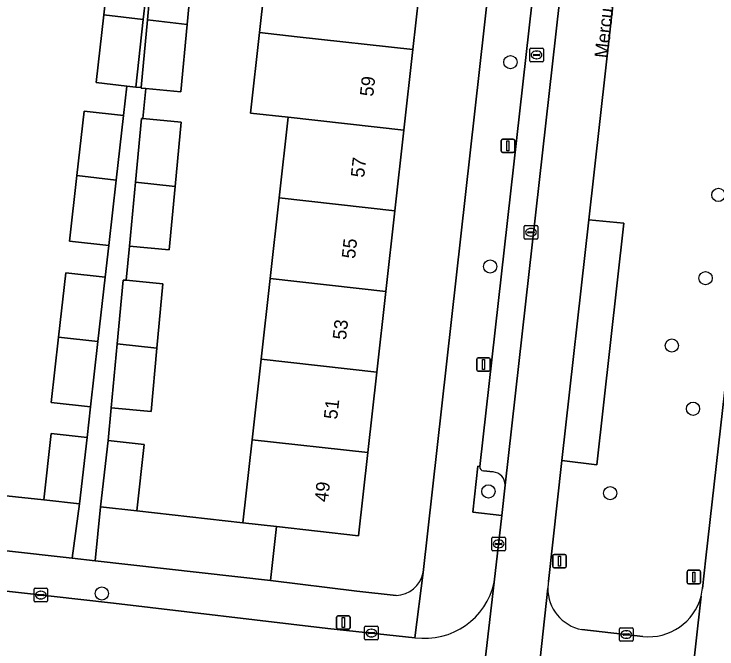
# Model space of a CAD drawing. Extents: x 161928 to 163071, y 386474 to 387428.
# Drawn here: x 162242.6 to 162294.6, y 386837.4 to 386884.4 of the extents above; entities that cross this region are included whole.
import ezdxf

# ---------------------------------------------------------------- set-up
doc = ezdxf.new("R2010")
doc.units = 0
for name, color, linetype in [('IMGEO_Berm_groen', 7, 'Continuous'), ('IMGEO_Boom', 7, 'Continuous'), ('IMGEO_Erf', 7, 'Continuous'), ('IMGEO_Groenvoorziening', 7, 'Continuous'), ('IMGEO_Kolk', 7, 'Continuous'), ('IMGEO_Lichtmast', 7, 'Continuous'), ('IMGEO_Openbare_ruimte_label', 7, 'Continuous'), ('IMGEO_Pand', 7, 'Continuous'), ('IMGEO_Pand_nummerreeks', 7, 'Continuous'), ('IMGEO_Parkeervlak_open', 7, 'Continuous'), ('IMGEO_Rijbaan_lokaal_open', 7, 'Continuous'), ('IMGEO_Rioolput', 7, 'Continuous'), ('IMGEO_Voetpad_open', 7, 'Continuous')]:
    doc.layers.add(name, color=color, linetype=linetype)

msp = doc.modelspace()

# ---------------------------------------------------------------- linework, layer by layer
at = {"layer": 'IMGEO_Berm_groen'}
for points in [[(162295.85, 386964.979), (162295.462, 386961.436), (162295.08, 386957.884), (162297.642, 386957.598), (162295.617, 386939.703), (162293.056, 386940.001), (162285.144, 386869.204), (162287.724, 386868.941), (162285.731, 386851.066), (162283.151, 386851.378), (162282.158, 386842.431)], [(162293.554, 386841.928), (162293.809, 386844.193), (162299.377, 386893.49), (162296.758, 386893.764), (162298.724, 386911.513)], [(162277.087, 386850.951), (162276.936, 386850.98), (162276.572, 386847.562), (162278.711, 386847.315), (162278.952, 386849.57)], [(162278.064, 386850.541), (162277.348, 386850.619)], [(162284.621, 386838.88), (162289.132, 386838.377)]]:
    msp.add_lwpolyline(points, dxfattribs=at)
for centre, radius, start, end in [((162277.388, 386850.919), 0.303, 173.9352, 262.4098), ((162278.011, 386849.601), 0.942, 358.1276, 86.7595), ((162285.107, 386841.925), 2.993, 170.2592, 179.4386), ((162285.207, 386841.916), 3.092, 179.2985, 259.0771), ((162289.496, 386842.369), 4.082, 345.7335, 353.7996), ((162289.577, 386842.351), 3.999, 263.6065, 345.6982)]:
    msp.add_arc(centre, radius, start, end, dxfattribs=at)
at = {"layer": 'IMGEO_Boom'}
for centre in [(162279.345, 386880.858), (162294.728, 386871.036), (162277.85, 386865.738), (162293.78, 386864.88), (162291.285, 386859.891), (162292.851, 386855.219), (162277.718, 386849.103), (162286.725, 386848.967), (162249.13, 386841.548)]:
    msp.add_circle(centre, 0.489, dxfattribs=at)
at = {"layer": 'IMGEO_Erf'}
for points in [[(162272.9, 386843.099), (162279.836, 386905.223), (162274.804, 386905.82), (162274.118, 386899.673), (162273.453, 386893.71), (162272.788, 386887.747), (162272.123, 386881.784), (162271.458, 386875.822), (162270.793, 386869.859), (162270.128, 386863.896), (162269.462, 386857.933), (162268.797, 386851.97), (162268.112, 386845.826), (162262.05, 386846.502), (162261.606, 386842.521), (162267.991, 386841.725), (162270.892, 386841.406)], [(162255.855, 386888.118), (162255.441, 386883.655), (162254.978, 386878.665), (162252.382, 386878.905), (162252.176, 386876.679), (162255.001, 386876.417), (162254.559, 386871.653), (162254.124, 386866.963), (162251.177, 386867.237), (162250.944, 386864.718), (162253.65, 386864.467), (162253.208, 386859.703), (162252.773, 386855.013), (162249.826, 386855.287), (162249.589, 386852.863), (162252.264, 386852.565), (162251.718, 386847.674), (162259.56, 386846.78), (162260.246, 386852.925), (162260.911, 386858.888), (162261.576, 386864.851), (162262.241, 386870.814), (162262.907, 386876.777), (162260.12, 386877.088), (162260.785, 386883.05), (162261.45, 386889.013)], [(162236.439, 386849.378), (162244.833, 386848.474), (162245.382, 386853.393), (162248.038, 386853.096), (162248.306, 386855.351), (162245.392, 386855.677), (162245.933, 386860.521), (162246.464, 386865.276), (162249.378, 386864.951), (162249.657, 386867.301), (162246.743, 386867.627), (162247.284, 386872.471), (162247.815, 386877.226), (162250.729, 386876.901), (162250.974, 386879.094), (162248.715, 386879.346), (162249.274, 386884.348), (162249.773, 386888.811)], [(162252.699, 386888.484), (162252.2, 386884.015), (162251.642, 386879.019), (162252.034, 386878.983), (162252.498, 386883.981), (162252.908, 386888.391)]]:
    msp.add_lwpolyline(points, dxfattribs=at)
msp.add_arc((162270.815, 386843.534), 2.13, 272.0613, 348.209, dxfattribs=at)
at = {"layer": 'IMGEO_Groenvoorziening'}
for points in [[(162246.945, 386844.164), (162247.49, 386848.178), (162244.833, 386848.474), (162236.439, 386849.378), (162231.888, 386849.896), (162231.457, 386845.899)], [(162261.606, 386842.521), (162262.05, 386846.502), (162259.56, 386846.78), (162251.718, 386847.674), (162249.043, 386847.972), (162248.649, 386843.973)]]:
    msp.add_lwpolyline(points, close=True, dxfattribs=at)
at = {"layer": 'IMGEO_Kolk'}
for p, q in [((162280.367, 386867.845), (162280.367, 386868.697)), ((162280.442, 386868.771), (162281.294, 386868.771)), ((162281.368, 386868.697), (162281.368, 386867.845)), ((162280.626, 386868.265), (162280.626, 386868.277)), ((162281.064, 386868.228), (162280.666, 386868.228)), ((162280.669, 386868.314), (162281.067, 386868.314)), ((162280.855, 386868.551), (162280.88, 386868.551)), ((162281.11, 386868.277), (162281.11, 386868.265)), ((162281.294, 386867.771), (162280.442, 386867.771)), ((162280.878, 386867.991), (162280.853, 386867.991)), ((162278.047, 386845.717), (162278.899, 386845.717)), ((162277.972, 386844.791), (162277.972, 386845.643)), ((162278.231, 386845.211), (162278.231, 386845.223)), ((162278.669, 386845.174), (162278.271, 386845.174)), ((162278.274, 386845.26), (162278.672, 386845.26)), ((162278.46, 386845.497), (162278.485, 386845.497)), ((162278.715, 386845.223), (162278.715, 386845.211)), ((162278.973, 386845.643), (162278.973, 386844.791)), ((162278.899, 386844.717), (162278.047, 386844.717)), ((162278.483, 386844.937), (162278.458, 386844.937)), ((162244.118, 386841.01), (162244.118, 386841.862)), ((162244.193, 386841.936), (162245.045, 386841.936)), ((162244.606, 386841.716), (162244.631, 386841.716)), ((162245.119, 386841.862), (162245.119, 386841.01)), ((162244.377, 386841.43), (162244.377, 386841.442)), ((162244.815, 386841.393), (162244.417, 386841.393)), ((162244.42, 386841.479), (162244.818, 386841.479)), ((162244.629, 386841.156), (162244.604, 386841.156)), ((162244.861, 386841.442), (162244.861, 386841.43)), ((162245.045, 386840.936), (162244.193, 386840.936)), ((162268.566, 386838.199), (162268.566, 386839.051)), ((162268.641, 386839.125), (162269.493, 386839.125)), ((162269.567, 386839.051), (162269.567, 386838.199)), ((162287.411, 386838.09), (162287.411, 386838.942)), ((162287.486, 386839.016), (162288.338, 386839.016)), ((162288.412, 386838.942), (162288.412, 386838.09)), ((162268.825, 386838.619), (162268.825, 386838.631)), ((162269.263, 386838.582), (162268.865, 386838.582)), ((162268.868, 386838.668), (162269.266, 386838.668)), ((162269.054, 386838.905), (162269.079, 386838.905)), ((162269.309, 386838.631), (162269.309, 386838.619)), ((162287.67, 386838.51), (162287.67, 386838.522)), ((162288.108, 386838.473), (162287.71, 386838.473)), ((162287.713, 386838.559), (162288.111, 386838.559)), ((162287.899, 386838.796), (162287.924, 386838.796)), ((162288.154, 386838.522), (162288.154, 386838.51)), ((162269.493, 386838.125), (162268.641, 386838.125)), ((162269.077, 386838.345), (162269.052, 386838.345)), ((162288.338, 386838.016), (162287.486, 386838.016)), ((162287.922, 386838.236), (162287.897, 386838.236))]:
    msp.add_line(p, q, dxfattribs=at)
for points in [[(162280.367, 386867.845), (162280.367, 386868.697)], [(162280.442, 386868.771), (162281.294, 386868.771)], [(162281.368, 386868.697), (162281.368, 386867.845)], [(162281.294, 386867.771), (162280.442, 386867.771)], [(162278.047, 386845.717), (162278.899, 386845.717)], [(162277.972, 386844.791), (162277.972, 386845.643)], [(162278.973, 386845.643), (162278.973, 386844.791)], [(162278.899, 386844.717), (162278.047, 386844.717)], [(162244.118, 386841.01), (162244.118, 386841.862)], [(162244.193, 386841.936), (162245.045, 386841.936)], [(162245.119, 386841.862), (162245.119, 386841.01)], [(162245.045, 386840.936), (162244.193, 386840.936)], [(162268.566, 386838.199), (162268.566, 386839.051)], [(162268.641, 386839.125), (162269.493, 386839.125)], [(162269.567, 386839.051), (162269.567, 386838.199)], [(162287.411, 386838.09), (162287.411, 386838.942)], [(162287.486, 386839.016), (162288.338, 386839.016)], [(162288.412, 386838.942), (162288.412, 386838.09)], [(162269.493, 386838.125), (162268.641, 386838.125)], [(162288.338, 386838.016), (162287.486, 386838.016)]]:
    msp.add_lwpolyline(points, dxfattribs=at)
for centre, radius, start, end in [((162280.444, 386868.695), 0.0765, 91.552, 178.448), ((162280.444, 386868.695), 0.0765, 91.552, 178.448), ((162281.292, 386868.695), 0.0765, 1.552, 88.448), ((162281.292, 386868.695), 0.0765, 1.552, 88.448), ((162280.666, 386868.274), 0.0403, 85.8775, 175.7526), ((162280.663, 386868.264), 0.0366, 178.938, 274.7102), ((162281.067, 386868.271), 0.043, 264.8664, 352.4533), ((162281.071, 386868.276), 0.0386, 1.7309, 96.639), ((162280.444, 386867.847), 0.0765, 181.552, 268.448), ((162280.444, 386867.847), 0.0765, 181.552, 268.448), ((162281.292, 386867.847), 0.0765, 271.552, 358.448), ((162281.292, 386867.847), 0.0765, 271.552, 358.448), ((162278.049, 386845.641), 0.0765, 91.552, 178.448), ((162278.049, 386845.641), 0.0765, 91.552, 178.448), ((162278.897, 386845.641), 0.0765, 1.552, 88.448), ((162278.897, 386845.641), 0.0765, 1.552, 88.448), ((162278.271, 386845.22), 0.0403, 85.8775, 175.7526), ((162278.268, 386845.21), 0.0366, 178.938, 274.7102), ((162278.672, 386845.217), 0.043, 264.8664, 352.4533), ((162278.676, 386845.222), 0.0386, 1.7309, 96.639), ((162278.049, 386844.793), 0.0765, 181.552, 268.448), ((162278.049, 386844.793), 0.0765, 181.552, 268.448), ((162278.897, 386844.793), 0.0765, 271.552, 358.448), ((162278.897, 386844.793), 0.0765, 271.552, 358.448), ((162244.195, 386841.86), 0.0765, 91.552, 178.448), ((162244.195, 386841.86), 0.0765, 91.552, 178.448), ((162245.043, 386841.86), 0.0765, 1.552, 88.448), ((162245.043, 386841.86), 0.0765, 1.552, 88.448), ((162244.195, 386841.012), 0.0765, 181.552, 268.448), ((162244.195, 386841.012), 0.0765, 181.552, 268.448), ((162244.417, 386841.439), 0.0403, 85.8775, 175.7526), ((162244.414, 386841.429), 0.0366, 178.938, 274.7102), ((162244.818, 386841.436), 0.043, 264.8664, 352.4533), ((162244.822, 386841.441), 0.0386, 1.7309, 96.639), ((162245.043, 386841.012), 0.0765, 271.552, 358.448), ((162245.043, 386841.012), 0.0765, 271.552, 358.448), ((162268.643, 386839.049), 0.0765, 91.552, 178.448), ((162268.643, 386839.049), 0.0765, 91.552, 178.448), ((162269.491, 386839.049), 0.0765, 1.552, 88.448), ((162269.491, 386839.049), 0.0765, 1.552, 88.448), ((162287.488, 386838.94), 0.0765, 91.552, 178.448), ((162287.488, 386838.94), 0.0765, 91.552, 178.448), ((162288.336, 386838.94), 0.0765, 1.552, 88.448), ((162288.336, 386838.94), 0.0765, 1.552, 88.448), ((162268.865, 386838.628), 0.0403, 85.8775, 175.7526), ((162268.862, 386838.618), 0.0366, 178.938, 274.7102), ((162269.266, 386838.625), 0.043, 264.8664, 352.4533), ((162269.27, 386838.63), 0.0386, 1.7309, 96.639), ((162287.71, 386838.519), 0.0403, 85.8775, 175.7526), ((162287.707, 386838.509), 0.0366, 178.938, 274.7102), ((162288.111, 386838.516), 0.043, 264.8664, 352.4533), ((162288.115, 386838.521), 0.0386, 1.7309, 96.639), ((162268.643, 386838.201), 0.0765, 181.552, 268.448), ((162268.643, 386838.201), 0.0765, 181.552, 268.448), ((162269.491, 386838.201), 0.0765, 271.552, 358.448), ((162269.491, 386838.201), 0.0765, 271.552, 358.448), ((162287.488, 386838.092), 0.0765, 181.552, 268.448), ((162287.488, 386838.092), 0.0765, 181.552, 268.448), ((162288.336, 386838.092), 0.0765, 271.552, 358.448), ((162288.336, 386838.092), 0.0765, 271.552, 358.448)]:
    msp.add_arc(centre, radius, start, end, dxfattribs=at)
for centre, major_axis, ratio, start_param, end_param in [((162280.854, 386868.271), (-0.387, 0.002), 0.722429, 4.712389, 7.853982), ((162280.879, 386868.271), (-0.39, 0.002), 0.717154, 1.570796, 4.712389), ((162278.459, 386845.217), (-0.387, 0.002), 0.722429, 4.712389, 7.853982), ((162278.484, 386845.217), (-0.39, 0.002), 0.717154, 1.570796, 4.712389), ((162244.605, 386841.436), (-0.387, 0.002), 0.722429, 4.712389, 7.853982), ((162244.63, 386841.436), (-0.39, 0.002), 0.717154, 1.570796, 4.712389), ((162269.053, 386838.625), (-0.387, 0.002), 0.722429, 4.712389, 7.853982), ((162269.078, 386838.625), (-0.39, 0.002), 0.717154, 1.570796, 4.712389), ((162287.898, 386838.516), (-0.387, 0.002), 0.722429, 4.712389, 7.853982), ((162287.923, 386838.516), (-0.39, 0.002), 0.717154, 1.570796, 4.712389)]:
    msp.add_ellipse(centre, major_axis=major_axis, ratio=ratio, start_param=start_param, end_param=end_param, dxfattribs=at)
at = {"layer": 'IMGEO_Lichtmast'}
for p, q in [((162278.671, 386874.265), (162278.671, 386875.065)), ((162278.671, 386875.065), (162278.671, 386874.265)), ((162278.771, 386875.165), (162279.561, 386875.165)), ((162279.561, 386875.165), (162278.771, 386875.165)), ((162279.661, 386875.065), (162279.661, 386874.265)), ((162279.661, 386874.265), (162279.661, 386875.065)), ((162279.561, 386874.165), (162278.771, 386874.165)), ((162278.771, 386874.165), (162279.561, 386874.165)), ((162276.858, 386858.088), (162276.858, 386858.888)), ((162276.858, 386858.888), (162276.858, 386858.088)), ((162276.958, 386858.988), (162277.748, 386858.988)), ((162277.748, 386858.988), (162276.958, 386858.988)), ((162277.848, 386858.888), (162277.848, 386858.088)), ((162277.848, 386858.088), (162277.848, 386858.888)), ((162277.748, 386857.988), (162276.958, 386857.988)), ((162276.958, 386857.988), (162277.748, 386857.988)), ((162282.482, 386843.545), (162282.482, 386844.345)), ((162282.482, 386844.345), (162282.482, 386843.545)), ((162282.582, 386844.445), (162283.372, 386844.445)), ((162283.372, 386844.445), (162282.582, 386844.445)), ((162283.472, 386844.345), (162283.472, 386843.545)), ((162283.472, 386843.545), (162283.472, 386844.345)), ((162283.372, 386843.445), (162282.582, 386843.445)), ((162282.582, 386843.445), (162283.372, 386843.445)), ((162292.422, 386842.364), (162292.422, 386843.164)), ((162292.422, 386843.164), (162292.422, 386842.364)), ((162292.522, 386843.264), (162293.312, 386843.264)), ((162293.312, 386843.264), (162292.522, 386843.264)), ((162293.412, 386843.164), (162293.412, 386842.364)), ((162293.412, 386842.364), (162293.412, 386843.164)), ((162293.312, 386842.264), (162292.522, 386842.264)), ((162292.522, 386842.264), (162293.312, 386842.264)), ((162266.496, 386839.008), (162266.496, 386839.808)), ((162266.496, 386839.808), (162266.496, 386839.008)), ((162266.596, 386839.908), (162267.386, 386839.908)), ((162267.386, 386839.908), (162266.596, 386839.908)), ((162267.486, 386839.808), (162267.486, 386839.008)), ((162267.486, 386839.008), (162267.486, 386839.808)), ((162267.386, 386838.908), (162266.596, 386838.908)), ((162266.596, 386838.908), (162267.386, 386838.908))]:
    msp.add_line(p, q, dxfattribs=at)
for points in [[(162279.091, 386875.04), (162279.241, 386875.04), (162279.241, 386874.29), (162279.091, 386874.29), (162279.091, 386875.04)], [(162277.278, 386858.863), (162277.428, 386858.863), (162277.428, 386858.113), (162277.278, 386858.113), (162277.278, 386858.863)], [(162282.902, 386844.32), (162283.052, 386844.32), (162283.052, 386843.57), (162282.902, 386843.57), (162282.902, 386844.32)], [(162292.842, 386843.139), (162292.992, 386843.139), (162292.992, 386842.389), (162292.842, 386842.389), (162292.842, 386843.139)], [(162266.916, 386839.783), (162267.066, 386839.783), (162267.066, 386839.033), (162266.916, 386839.033), (162266.916, 386839.783)]]:
    msp.add_lwpolyline(points, dxfattribs=at)
for centre, start, end in [((162278.771, 386875.065), 90, 180), ((162278.771, 386875.065), 90, 180), ((162279.561, 386875.065), 0, 90), ((162279.561, 386875.065), 360, 90), ((162278.771, 386874.265), 180, 270), ((162278.771, 386874.265), 180, 270), ((162279.561, 386874.265), 270, 0), ((162279.561, 386874.265), 270, 0), ((162276.958, 386858.888), 90, 180), ((162276.958, 386858.888), 90, 180), ((162277.748, 386858.888), 0, 90), ((162277.748, 386858.888), 360, 90), ((162276.958, 386858.088), 180, 270), ((162276.958, 386858.088), 180, 270), ((162277.748, 386858.088), 270, 0), ((162277.748, 386858.088), 270, 0), ((162282.582, 386844.345), 90, 180), ((162282.582, 386844.345), 90, 180), ((162283.372, 386844.345), 0, 90), ((162283.372, 386844.345), 360, 90), ((162282.582, 386843.545), 180, 270), ((162282.582, 386843.545), 180, 270), ((162283.372, 386843.545), 270, 0), ((162283.372, 386843.545), 270, 0), ((162292.522, 386843.164), 90, 180), ((162292.522, 386843.164), 90, 180), ((162293.312, 386843.164), 0, 90), ((162293.312, 386843.164), 360, 90), ((162292.522, 386842.364), 180, 270), ((162292.522, 386842.364), 180, 270), ((162293.312, 386842.364), 270, 0), ((162293.312, 386842.364), 270, 0), ((162266.596, 386839.808), 90, 180), ((162266.596, 386839.808), 90, 180), ((162267.386, 386839.808), 0, 90), ((162267.386, 386839.808), 360, 90), ((162266.596, 386839.008), 180, 270), ((162266.596, 386839.008), 180, 270), ((162267.386, 386839.008), 270, 0), ((162267.386, 386839.008), 270, 0)]:
    msp.add_arc(centre, 0.1, start, end, dxfattribs=at)
at = {"layer": 'IMGEO_Pand'}
for points in [[(162272.788, 386887.747), (162264.237, 386888.702), (162261.45, 386889.013), (162260.785, 386883.05), (162263.572, 386882.739), (162272.123, 386881.784)], [(162252.2, 386884.015), (162252.699, 386888.484), (162249.773, 386888.811), (162249.274, 386884.348)], [(162255.441, 386883.655), (162255.855, 386888.118), (162252.908, 386888.391), (162252.498, 386883.981)], [(162252.2, 386884.015), (162249.274, 386884.348), (162248.715, 386879.346), (162250.974, 386879.094), (162251.642, 386879.019)], [(162255.441, 386883.655), (162252.498, 386883.981), (162252.034, 386878.983), (162252.03, 386878.938), (162252.382, 386878.905), (162254.978, 386878.665)], [(162272.123, 386881.784), (162263.572, 386882.739), (162260.785, 386883.05), (162260.12, 386877.088), (162262.907, 386876.777), (162271.458, 386875.822)], [(162250.729, 386876.901), (162247.815, 386877.226), (162247.284, 386872.471), (162250.198, 386872.139)], [(162255.001, 386876.417), (162252.176, 386876.679), (162252.054, 386876.69), (162251.617, 386871.979), (162254.559, 386871.653)], [(162270.793, 386869.859), (162271.458, 386875.822), (162262.907, 386876.777), (162262.241, 386870.814)], [(162246.743, 386867.627), (162249.657, 386867.301), (162250.198, 386872.139), (162247.284, 386872.471)], [(162251.177, 386867.237), (162254.124, 386866.963), (162254.559, 386871.653), (162251.617, 386871.979)], [(162262.241, 386870.814), (162261.576, 386864.851), (162270.128, 386863.896), (162270.793, 386869.859)], [(162248.847, 386860.189), (162249.378, 386864.951), (162246.464, 386865.276), (162245.933, 386860.521)], [(162253.65, 386864.467), (162250.944, 386864.718), (162250.703, 386864.74), (162250.266, 386860.029), (162253.208, 386859.703)], [(162261.576, 386864.851), (162260.911, 386858.888), (162269.462, 386857.933), (162270.128, 386863.896)], [(162245.933, 386860.521), (162245.392, 386855.677), (162248.306, 386855.351), (162248.847, 386860.189)], [(162250.266, 386860.029), (162249.826, 386855.287), (162252.773, 386855.013), (162253.208, 386859.703)], [(162260.911, 386858.888), (162260.246, 386852.925), (162268.797, 386851.97), (162269.462, 386857.933)], [(162248.038, 386853.096), (162245.382, 386853.393), (162244.833, 386848.474), (162247.49, 386848.178)], [(162252.264, 386852.565), (162249.589, 386852.863), (162249.043, 386847.972), (162251.718, 386847.674)], [(162260.246, 386852.925), (162259.56, 386846.78), (162262.05, 386846.502), (162268.112, 386845.826), (162268.797, 386851.97)]]:
    msp.add_lwpolyline(points, close=True, dxfattribs=at)
at = {"layer": 'IMGEO_Parkeervlak_open'}
for points in [[(162278.952, 386849.57), (162286.473, 386916.537)], [(162284.366, 386915.643), (162277.087, 386850.951)], [(162277.348, 386850.619), (162278.064, 386850.541)]]:
    msp.add_lwpolyline(points, dxfattribs=at)
msp.add_lwpolyline([(162283.151, 386851.378), (162285.731, 386851.066), (162287.724, 386868.941), (162285.144, 386869.204)], close=True, dxfattribs=at)
for centre, radius, start, end in [((162277.388, 386850.919), 0.303, 173.9352, 262.4098), ((162278.011, 386849.601), 0.942, 358.1276, 86.7595)]:
    msp.add_arc(centre, radius, start, end, dxfattribs=at)
at = {"layer": 'IMGEO_Rijbaan_lokaal_open'}
for points in [[(162310.198, 386959.221), (162306.752, 386959.631), (162301.337, 386911.211), (162299.377, 386893.49), (162293.809, 386844.193), (162293.554, 386841.928)], [(162250, 386840.828), (162215.943, 386844.646), (162207.117, 386845.636), (162198.333, 386846.547), (162189.972, 386847.459), (162186.215, 386847.869), (162184.325, 386848.075), (162180.548, 386848.487), (162180.286, 386848.516)], [(162276.448, 386827.713), (162278.151, 386842.384)], [(162282.115, 386841.954), (162280.726, 386829.213)], [(162293.452, 386841.363), (162291.861, 386827.034), (162291.687, 386825.48), (162291.453, 386823.384), (162288.283, 386795.004)], [(162291.861, 386827.034), (162293.452, 386841.363)], [(162272.289, 386838.281), (162265.838, 386838.97), (162250, 386840.828)], [(162289.132, 386838.377), (162284.621, 386838.88)]]:
    msp.add_lwpolyline(points, dxfattribs=at)
for centre, radius, start, end in [((162273.009, 386843.491), 5.26, 262.1309, 347.8479), ((162285.207, 386841.916), 3.092, 179.2985, 259.0771), ((162289.496, 386842.369), 4.082, 345.7335, 353.7996), ((162289.577, 386842.351), 3.999, 263.6065, 345.6982)]:
    msp.add_arc(centre, radius, start, end, dxfattribs=at)
at = {"layer": 'IMGEO_Rioolput'}
for p, q in [((162280.78, 386880.968), (162280.78, 386881.82)), ((162280.855, 386881.894), (162281.707, 386881.894)), ((162281.268, 386881.674), (162281.293, 386881.674)), ((162281.781, 386881.82), (162281.781, 386880.968)), ((162281.039, 386881.388), (162281.039, 386881.4)), ((162281.477, 386881.351), (162281.079, 386881.351)), ((162281.082, 386881.437), (162281.48, 386881.437)), ((162281.291, 386881.114), (162281.266, 386881.114)), ((162281.523, 386881.4), (162281.523, 386881.388)), ((162281.707, 386880.894), (162280.855, 386880.894))]:
    msp.add_line(p, q, dxfattribs=at)
for points in [[(162280.78, 386880.968), (162280.78, 386881.82)], [(162280.855, 386881.894), (162281.707, 386881.894)], [(162281.781, 386881.82), (162281.781, 386880.968)], [(162281.707, 386880.894), (162280.855, 386880.894)]]:
    msp.add_lwpolyline(points, dxfattribs=at)
for centre, radius, start, end in [((162280.857, 386881.818), 0.0765, 91.552, 178.448), ((162280.857, 386881.818), 0.0765, 91.552, 178.448), ((162281.705, 386881.818), 0.0765, 1.552, 88.448), ((162281.705, 386881.818), 0.0765, 1.552, 88.448), ((162281.079, 386881.397), 0.0403, 85.8775, 175.7526), ((162281.076, 386881.387), 0.0366, 178.938, 274.7102), ((162281.48, 386881.394), 0.043, 264.8664, 352.4533), ((162281.484, 386881.399), 0.0386, 1.7309, 96.639), ((162280.857, 386880.97), 0.0765, 181.552, 268.448), ((162280.857, 386880.97), 0.0765, 181.552, 268.448), ((162281.705, 386880.97), 0.0765, 271.552, 358.448), ((162281.705, 386880.97), 0.0765, 271.552, 358.448)]:
    msp.add_arc(centre, radius, start, end, dxfattribs=at)
for centre, major_axis, ratio, start_param, end_param in [((162281.267, 386881.394), (-0.387, 0.002), 0.722429, 4.712389, 7.853982), ((162281.292, 386881.394), (-0.39, 0.002), 0.717154, 1.570796, 4.712389)]:
    msp.add_ellipse(centre, major_axis=major_axis, ratio=ratio, start_param=start_param, end_param=end_param, dxfattribs=at)
at = {"layer": 'IMGEO_Voetpad_open'}
for points in [[(162282.158, 386842.431), (162283.151, 386851.378), (162285.144, 386869.204), (162293.056, 386940.001), (162295.08, 386957.884), (162295.462, 386961.436), (162291.491, 386961.884), (162291.401, 386961.084), (162291.062, 386958.054), (162288.606, 386935.712), (162288.483, 386934.595)], [(162286.652, 386918.105), (162286.473, 386916.537), (162278.952, 386849.57), (162278.711, 386847.315), (162278.151, 386842.384), (162276.448, 386827.713)], [(162278.151, 386842.384), (162278.711, 386847.315), (162276.572, 386847.562), (162276.936, 386850.98), (162277.087, 386850.951), (162284.366, 386915.643)], [(162280.035, 386907.002), (162279.836, 386905.223), (162272.9, 386843.099), (162272.289, 386838.281)], [(162219.524, 386847.232), (162217.58, 386847.442), (162214.37, 386847.825), (162211.872, 386848.108), (162211.585, 386845.638), (162215.998, 386845.143), (162215.943, 386844.646), (162250, 386840.828), (162265.838, 386838.97), (162272.289, 386838.281), (162272.9, 386843.099)], [(162261.606, 386842.521), (162248.649, 386843.973), (162246.945, 386844.164), (162231.457, 386845.899), (162226.925, 386846.407)], [(162270.892, 386841.406), (162267.991, 386841.725), (162261.606, 386842.521)], [(162280.726, 386829.213), (162282.115, 386841.954)]]:
    msp.add_lwpolyline(points, dxfattribs=at)
msp.add_lwpolyline([(162251.177, 386867.237), (162251.617, 386871.979), (162252.054, 386876.69), (162252.176, 386876.679), (162252.382, 386878.905), (162252.03, 386878.938), (162252.034, 386878.983), (162251.642, 386879.019), (162250.974, 386879.094), (162250.729, 386876.901), (162250.198, 386872.139), (162249.657, 386867.301), (162249.378, 386864.951), (162248.847, 386860.189), (162248.306, 386855.351), (162248.038, 386853.096), (162247.49, 386848.178), (162246.945, 386844.164), (162248.649, 386843.973), (162249.043, 386847.972), (162249.589, 386852.863), (162249.826, 386855.287), (162250.266, 386860.029), (162250.703, 386864.74), (162250.944, 386864.718)], close=True, dxfattribs=at)
for centre, radius, start, end in [((162270.815, 386843.534), 2.13, 272.0613, 348.209), ((162273.009, 386843.491), 5.26, 262.1309, 347.8479), ((162285.107, 386841.925), 2.993, 170.2592, 179.4386)]:
    msp.add_arc(centre, radius, start, end, dxfattribs=at)

# ---------------------------------------------------------------- texts
at = {"layer": 'IMGEO_Openbare_ruimte_label'}
msp.add_text('Mercuriuslaan', height=1, rotation=83.6851, dxfattribs=at).set_placement((162286.548, 386881.118))
at = {"layer": 'IMGEO_Pand_nummerreeks'}
for s, rotation, p in [('59', 83.6346, (162269.197, 386878.28)), ('57', 83.6353, (162268.527, 386872.282)), ('55', 83.6353, (162267.858, 386866.282)), ('53', 83.6353, (162267.189, 386860.283)), ('51', 83.6353, (162266.532, 386854.396)), ('49', 83.6353, (162265.85, 386848.284))]:
    msp.add_text(s, height=1, rotation=rotation, dxfattribs=at).set_placement(p)

doc.saveas('drawing.dxf')
